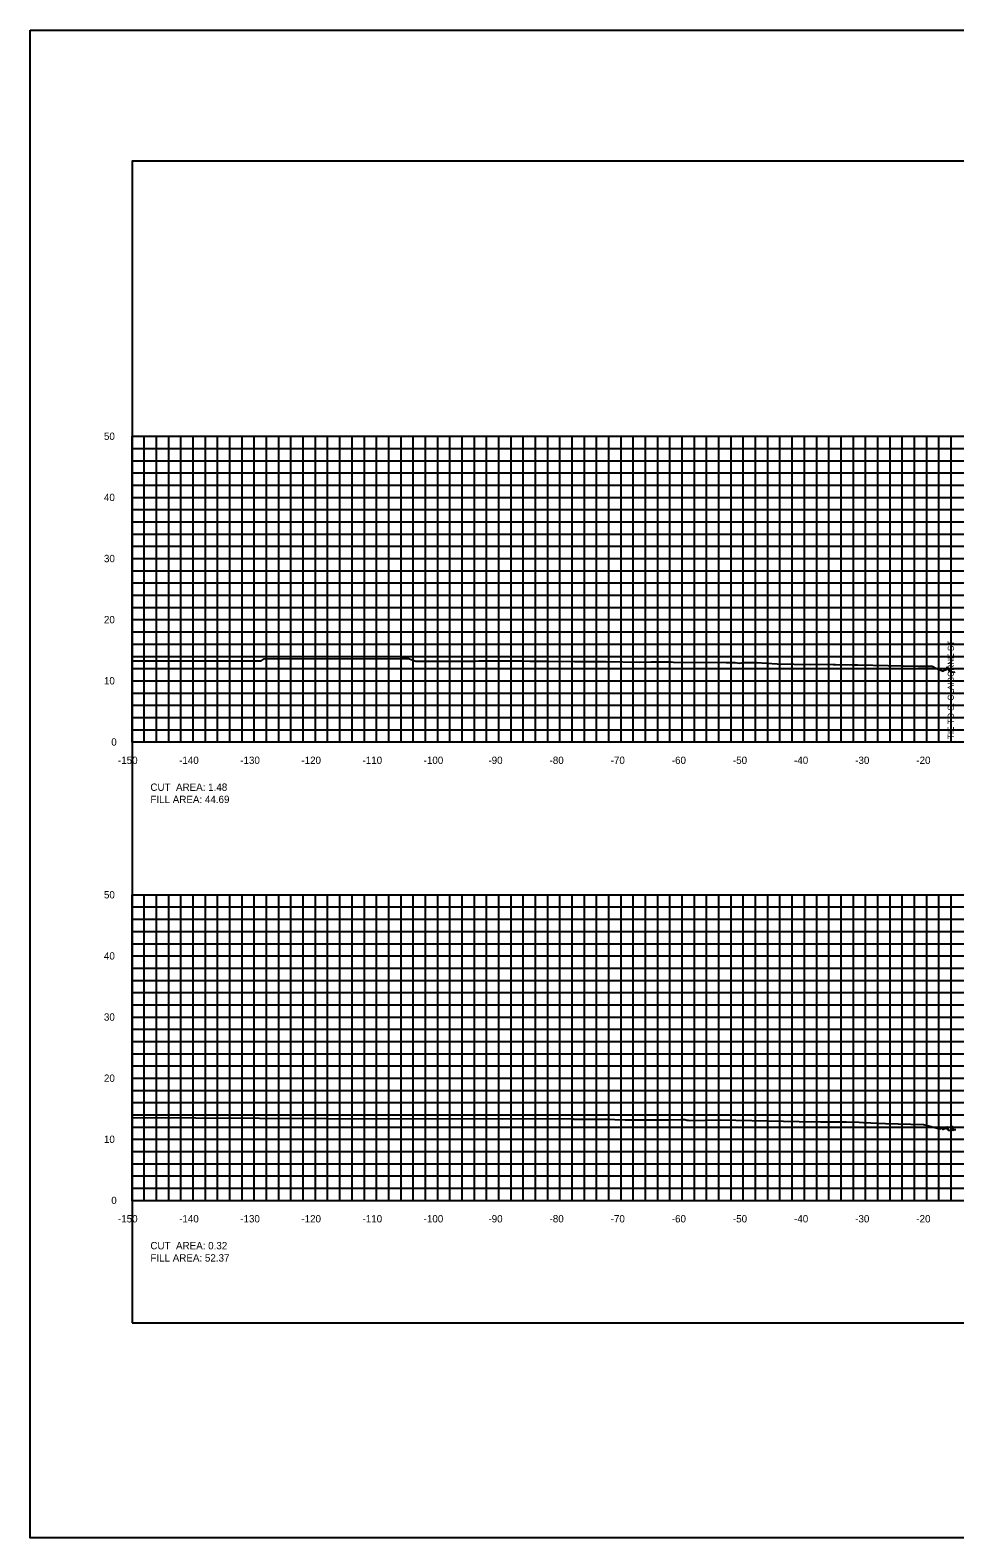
# Model space of a CAD drawing. Extents: x 1797518 to 1804843, y 248068 to 251132.
# Drawn here: x 1804164.3 to 1804315.6, y 250044.2 to 250290.9 of the extents above; entities that cross this region are included whole.
import ezdxf

# ---------------------------------------------------------------- set-up
doc = ezdxf.new("R2010")
doc.units = 0
for name, color, linetype in [('1', 7, 'Continuous'), ('10', 7, 'Continuous'), ('3', 7, 'Continuous'), ('31', 7, 'Continuous'), ('60', 7, 'Continuous'), ('ANNO-TXT', 7, 'Continuous'), ('Level 62', 7, 'Continuous'), ('M-ROADS', 7, 'Continuous')]:
    doc.layers.add(name, color=color, linetype=linetype)

msp = doc.modelspace()

# ---------------------------------------------------------------- linework, layer by layer
msp.add_lwpolyline([(1804181, 250079.43), (1804481, 250079.43), (1804481, 250269.43), (1804181, 250269.43)], close=True)
at = {"layer": '1'}
msp.add_lwpolyline([(1804164.33, 250290.86), (1804501.93, 250290.86), (1804501.93, 250044.24), (1804164.33, 250044.24)], close=True, dxfattribs=at)
at = {"layer": '60'}
for p, q in [((1804180.94, 250224.43), (1804181, 250224.43)), ((1804181, 250174.43), (1804181, 250224.43)), ((1804180.94, 250214.43), (1804181, 250214.43)), ((1804180.94, 250204.43), (1804181, 250204.43)), ((1804180.94, 250194.43), (1804181, 250194.43)), ((1804180.94, 250184.43), (1804181, 250184.43)), ((1804180.94, 250174.43), (1804181, 250174.43)), ((1804181, 250174.43), (1804481, 250174.43)), ((1804181, 250174.37), (1804181, 250174.43)), ((1804191, 250174.37), (1804191, 250174.43)), ((1804201, 250174.37), (1804201, 250174.43)), ((1804211, 250174.37), (1804211, 250174.43)), ((1804221, 250174.37), (1804221, 250174.43)), ((1804231, 250174.37), (1804231, 250174.43)), ((1804241, 250174.37), (1804241, 250174.43)), ((1804251, 250174.37), (1804251, 250174.43)), ((1804261, 250174.37), (1804261, 250174.43)), ((1804271, 250174.37), (1804271, 250174.43)), ((1804281, 250174.37), (1804281, 250174.43)), ((1804291, 250174.37), (1804291, 250174.43)), ((1804301, 250174.37), (1804301, 250174.43)), ((1804311, 250174.37), (1804311, 250174.43)), ((1804180.94, 250149.43), (1804181, 250149.43)), ((1804181, 250099.43), (1804181, 250149.43)), ((1804180.94, 250139.43), (1804181, 250139.43)), ((1804180.94, 250129.43), (1804181, 250129.43)), ((1804180.94, 250119.43), (1804181, 250119.43)), ((1804180.94, 250109.43), (1804181, 250109.43)), ((1804180.94, 250099.43), (1804181, 250099.43)), ((1804181, 250099.43), (1804481, 250099.43)), ((1804181, 250099.37), (1804181, 250099.43)), ((1804191, 250099.37), (1804191, 250099.43)), ((1804201, 250099.37), (1804201, 250099.43)), ((1804211, 250099.37), (1804211, 250099.43)), ((1804221, 250099.37), (1804221, 250099.43)), ((1804231, 250099.37), (1804231, 250099.43)), ((1804241, 250099.37), (1804241, 250099.43)), ((1804251, 250099.37), (1804251, 250099.43)), ((1804261, 250099.37), (1804261, 250099.43)), ((1804271, 250099.37), (1804271, 250099.43)), ((1804281, 250099.37), (1804281, 250099.43)), ((1804291, 250099.37), (1804291, 250099.43)), ((1804301, 250099.37), (1804301, 250099.43)), ((1804311, 250099.37), (1804311, 250099.43))]:
    msp.add_line(p, q, dxfattribs=at)
at = {"layer": 'Level 62'}
for p, q in [((1804181, 250224.43), (1804481, 250224.43)), ((1804181, 250174.43), (1804181, 250224.43)), ((1804183, 250174.43), (1804183, 250224.43)), ((1804185, 250174.43), (1804185, 250224.43)), ((1804187, 250174.43), (1804187, 250224.43)), ((1804189, 250174.43), (1804189, 250224.43)), ((1804191, 250174.43), (1804191, 250224.43)), ((1804193, 250174.43), (1804193, 250224.43)), ((1804195, 250174.43), (1804195, 250224.43)), ((1804197, 250174.43), (1804197, 250224.43)), ((1804199, 250174.43), (1804199, 250224.43)), ((1804201, 250174.43), (1804201, 250224.43)), ((1804203, 250174.43), (1804203, 250224.43)), ((1804205, 250174.43), (1804205, 250224.43)), ((1804207, 250174.43), (1804207, 250224.43)), ((1804209, 250174.43), (1804209, 250224.43)), ((1804211, 250174.43), (1804211, 250224.43)), ((1804213, 250174.43), (1804213, 250224.43)), ((1804215, 250174.43), (1804215, 250224.43)), ((1804217, 250174.43), (1804217, 250224.43)), ((1804219, 250174.43), (1804219, 250224.43)), ((1804221, 250174.43), (1804221, 250224.43)), ((1804223, 250174.43), (1804223, 250224.43)), ((1804225, 250174.43), (1804225, 250224.43)), ((1804227, 250174.43), (1804227, 250224.43)), ((1804229, 250174.43), (1804229, 250224.43)), ((1804231, 250174.43), (1804231, 250224.43)), ((1804233, 250174.43), (1804233, 250224.43)), ((1804235, 250174.43), (1804235, 250224.43)), ((1804237, 250174.43), (1804237, 250224.43)), ((1804239, 250174.43), (1804239, 250224.43)), ((1804241, 250174.43), (1804241, 250224.43)), ((1804243, 250174.43), (1804243, 250224.43)), ((1804245, 250174.43), (1804245, 250224.43)), ((1804247, 250174.43), (1804247, 250224.43)), ((1804249, 250174.43), (1804249, 250224.43)), ((1804251, 250174.43), (1804251, 250224.43)), ((1804253, 250174.43), (1804253, 250224.43)), ((1804255, 250174.43), (1804255, 250224.43)), ((1804257, 250174.43), (1804257, 250224.43)), ((1804259, 250174.43), (1804259, 250224.43)), ((1804261, 250174.43), (1804261, 250224.43)), ((1804263, 250174.43), (1804263, 250224.43)), ((1804265, 250174.43), (1804265, 250224.43)), ((1804267, 250174.43), (1804267, 250224.43)), ((1804269, 250174.43), (1804269, 250224.43)), ((1804271, 250174.43), (1804271, 250224.43)), ((1804273, 250174.43), (1804273, 250224.43)), ((1804275, 250174.43), (1804275, 250224.43)), ((1804277, 250174.43), (1804277, 250224.43)), ((1804279, 250174.43), (1804279, 250224.43)), ((1804281, 250174.43), (1804281, 250224.43)), ((1804283, 250174.43), (1804283, 250224.43)), ((1804285, 250174.43), (1804285, 250224.43)), ((1804287, 250174.43), (1804287, 250224.43)), ((1804289, 250174.43), (1804289, 250224.43)), ((1804291, 250174.43), (1804291, 250224.43)), ((1804293, 250174.43), (1804293, 250224.43)), ((1804295, 250174.43), (1804295, 250224.43)), ((1804297, 250174.43), (1804297, 250224.43)), ((1804299, 250174.43), (1804299, 250224.43)), ((1804301, 250174.43), (1804301, 250224.43)), ((1804303, 250174.43), (1804303, 250224.43)), ((1804305, 250174.43), (1804305, 250224.43)), ((1804307, 250174.43), (1804307, 250224.43)), ((1804309, 250174.43), (1804309, 250224.43)), ((1804311, 250174.43), (1804311, 250224.43)), ((1804313, 250174.43), (1804313, 250224.43)), ((1804315, 250174.43), (1804315, 250224.43)), ((1804181, 250222.43), (1804481, 250222.43)), ((1804181, 250220.43), (1804481, 250220.43)), ((1804181, 250218.43), (1804481, 250218.43)), ((1804181, 250216.43), (1804481, 250216.43)), ((1804181, 250214.43), (1804481, 250214.43)), ((1804181, 250212.43), (1804481, 250212.43)), ((1804181, 250210.43), (1804481, 250210.43)), ((1804181, 250208.43), (1804481, 250208.43)), ((1804181, 250206.43), (1804481, 250206.43)), ((1804181, 250204.43), (1804481, 250204.43)), ((1804181, 250202.43), (1804481, 250202.43)), ((1804181, 250200.43), (1804481, 250200.43)), ((1804181, 250198.43), (1804481, 250198.43)), ((1804181, 250196.43), (1804481, 250196.43)), ((1804181, 250194.43), (1804481, 250194.43)), ((1804181, 250192.43), (1804481, 250192.43)), ((1804181, 250190.43), (1804481, 250190.43)), ((1804181, 250188.43), (1804481, 250188.43)), ((1804181, 250186.43), (1804481, 250186.43)), ((1804181, 250184.43), (1804481, 250184.43)), ((1804181, 250182.43), (1804481, 250182.43)), ((1804181, 250180.43), (1804481, 250180.43)), ((1804181, 250178.43), (1804481, 250178.43)), ((1804181, 250176.43), (1804481, 250176.43)), ((1804181, 250174.43), (1804481, 250174.43)), ((1804181, 250149.43), (1804481, 250149.43)), ((1804181, 250099.43), (1804181, 250149.43)), ((1804181, 250147.43), (1804481, 250147.43)), ((1804183, 250099.43), (1804183, 250149.43)), ((1804185, 250099.43), (1804185, 250149.43)), ((1804187, 250099.43), (1804187, 250149.43)), ((1804189, 250099.43), (1804189, 250149.43)), ((1804191, 250099.43), (1804191, 250149.43)), ((1804193, 250099.43), (1804193, 250149.43)), ((1804195, 250099.43), (1804195, 250149.43)), ((1804197, 250099.43), (1804197, 250149.43)), ((1804199, 250099.43), (1804199, 250149.43)), ((1804201, 250099.43), (1804201, 250149.43)), ((1804203, 250099.43), (1804203, 250149.43)), ((1804205, 250099.43), (1804205, 250149.43)), ((1804207, 250099.43), (1804207, 250149.43)), ((1804209, 250099.43), (1804209, 250149.43)), ((1804211, 250099.43), (1804211, 250149.43)), ((1804213, 250099.43), (1804213, 250149.43)), ((1804215, 250099.43), (1804215, 250149.43)), ((1804217, 250099.43), (1804217, 250149.43)), ((1804219, 250099.43), (1804219, 250149.43)), ((1804221, 250099.43), (1804221, 250149.43)), ((1804223, 250099.43), (1804223, 250149.43)), ((1804225, 250099.43), (1804225, 250149.43)), ((1804227, 250099.43), (1804227, 250149.43)), ((1804229, 250099.43), (1804229, 250149.43)), ((1804231, 250099.43), (1804231, 250149.43)), ((1804233, 250099.43), (1804233, 250149.43)), ((1804235, 250099.43), (1804235, 250149.43)), ((1804237, 250099.43), (1804237, 250149.43)), ((1804239, 250099.43), (1804239, 250149.43)), ((1804241, 250099.43), (1804241, 250149.43)), ((1804243, 250099.43), (1804243, 250149.43)), ((1804245, 250099.43), (1804245, 250149.43)), ((1804247, 250099.43), (1804247, 250149.43)), ((1804249, 250099.43), (1804249, 250149.43)), ((1804251, 250099.43), (1804251, 250149.43)), ((1804253, 250099.43), (1804253, 250149.43)), ((1804255, 250099.43), (1804255, 250149.43)), ((1804257, 250099.43), (1804257, 250149.43)), ((1804259, 250099.43), (1804259, 250149.43)), ((1804261, 250099.43), (1804261, 250149.43)), ((1804263, 250099.43), (1804263, 250149.43)), ((1804265, 250099.43), (1804265, 250149.43)), ((1804267, 250099.43), (1804267, 250149.43)), ((1804269, 250099.43), (1804269, 250149.43)), ((1804271, 250099.43), (1804271, 250149.43)), ((1804273, 250099.43), (1804273, 250149.43)), ((1804275, 250099.43), (1804275, 250149.43)), ((1804277, 250099.43), (1804277, 250149.43)), ((1804279, 250099.43), (1804279, 250149.43)), ((1804281, 250099.43), (1804281, 250149.43)), ((1804283, 250099.43), (1804283, 250149.43)), ((1804285, 250099.43), (1804285, 250149.43)), ((1804287, 250099.43), (1804287, 250149.43)), ((1804289, 250099.43), (1804289, 250149.43)), ((1804291, 250099.43), (1804291, 250149.43)), ((1804293, 250099.43), (1804293, 250149.43)), ((1804295, 250099.43), (1804295, 250149.43)), ((1804297, 250099.43), (1804297, 250149.43)), ((1804299, 250099.43), (1804299, 250149.43)), ((1804301, 250099.43), (1804301, 250149.43)), ((1804303, 250099.43), (1804303, 250149.43)), ((1804305, 250099.43), (1804305, 250149.43)), ((1804307, 250099.43), (1804307, 250149.43)), ((1804309, 250099.43), (1804309, 250149.43)), ((1804311, 250099.43), (1804311, 250149.43)), ((1804313, 250099.43), (1804313, 250149.43)), ((1804315, 250099.43), (1804315, 250149.43)), ((1804181, 250145.43), (1804481, 250145.43)), ((1804181, 250143.43), (1804481, 250143.43)), ((1804181, 250141.43), (1804481, 250141.43)), ((1804181, 250139.43), (1804481, 250139.43)), ((1804181, 250137.43), (1804481, 250137.43)), ((1804181, 250135.43), (1804481, 250135.43)), ((1804181, 250133.43), (1804481, 250133.43)), ((1804181, 250131.43), (1804481, 250131.43)), ((1804181, 250129.43), (1804481, 250129.43)), ((1804181, 250127.43), (1804481, 250127.43)), ((1804181, 250125.43), (1804481, 250125.43)), ((1804181, 250123.43), (1804481, 250123.43)), ((1804181, 250121.43), (1804481, 250121.43)), ((1804181, 250119.43), (1804481, 250119.43)), ((1804181, 250117.43), (1804481, 250117.43)), ((1804181, 250115.43), (1804481, 250115.43)), ((1804181, 250113.43), (1804481, 250113.43)), ((1804181, 250111.43), (1804481, 250111.43)), ((1804181, 250109.43), (1804481, 250109.43)), ((1804181, 250107.43), (1804481, 250107.43)), ((1804181, 250105.43), (1804481, 250105.43)), ((1804181, 250103.43), (1804481, 250103.43)), ((1804181, 250101.43), (1804481, 250101.43)), ((1804181, 250099.43), (1804481, 250099.43))]:
    msp.add_line(p, q, dxfattribs=at)
at = {"layer": 'M-ROADS'}
for points in [[(1804181, 250187.7), (1804184.47, 250187.71), (1804193.98, 250187.7), (1804195.99, 250187.72), (1804197.77, 250187.72), (1804198.56, 250187.71), (1804199.06, 250187.7), (1804199.33, 250187.72), (1804199.46, 250187.71), (1804200.33, 250187.71), (1804202.12, 250187.72), (1804202.62, 250188.02), (1804204.14, 250188.07), (1804204.79, 250188.01), (1804224.98, 250188.1), (1804226.23, 250188.07), (1804227.43, 250187.65), (1804233.85, 250187.63), (1804234.95, 250187.65), (1804235.67, 250187.66), (1804237.05, 250187.66), (1804237.71, 250187.67), (1804238.97, 250187.67), (1804240.2, 250187.68), (1804241.01, 250187.68), (1804242.66, 250187.68), (1804244.09, 250187.67), (1804244.85, 250187.67), (1804246.08, 250187.66), (1804247.67, 250187.65), (1804249.2, 250187.64), (1804253.36, 250187.58), (1804255.76, 250187.59), (1804256.2, 250187.59), (1804257.17, 250187.58), (1804258.01, 250187.58), (1804258.56, 250187.57), (1804264.09, 250187.5), (1804265.95, 250187.53), (1804269.18, 250187.51), (1804269.58, 250187.5), (1804278.2, 250187.44), (1804279.65, 250187.45), (1804280.4, 250187.3), (1804281.03, 250187.45), (1804282.28, 250187.42), (1804283.13, 250187.43), (1804283.18, 250187.41), (1804286.54, 250187.19), (1804292.04, 250187.12), (1804292.88, 250187.13), (1804295.72, 250187.07), (1804296.09, 250187.08), (1804298.83, 250187.04), (1804299.03, 250187.03), (1804299.74, 250187.02), (1804304.69, 250186.95), (1804309.61, 250186.83), (1804311.17, 250186.84), (1804311.92, 250186.83), (1804312.58, 250186.46), (1804313.68, 250186.03), (1804313.74, 250186.05), (1804313.89, 250186.16), (1804313.97, 250186.17), (1804314.02, 250186.2), (1804314.06, 250186.23), (1804314.09, 250186.23), (1804314.11, 250186.25), (1804314.13, 250186.25), (1804314.14, 250186.28), (1804314.16, 250186.28), (1804314.26, 250186.3), (1804314.29, 250186.34), (1804314.29, 250186.36), (1804314.29, 250186.34), (1804314.32, 250186.26), (1804314.34, 250186.64), (1804314.71, 250186), (1804314.94, 250185.86), (1804315.04, 250185.89), (1804315.05, 250185.89), (1804315.05, 250185.89), (1804315.05, 250185.88), (1804315.08, 250185.88), (1804315.09, 250185.87), (1804315.14, 250185.89), (1804315.19, 250185.87), (1804315.46, 250185.85), (1804315.67, 250185.92)], [(1804181, 250112.99), (1804201.87, 250112.87), (1804212.98, 250112.84), (1804241.67, 250112.77), (1804252.81, 250112.82), (1804253.05, 250112.82), (1804253.28, 250112.74), (1804254.52, 250112.73), (1804254.73, 250112.74), (1804254.87, 250112.74), (1804255.14, 250112.74), (1804255.27, 250112.74), (1804255.51, 250112.74), (1804255.75, 250112.74), (1804255.91, 250112.74), (1804256.23, 250112.74), (1804256.51, 250112.74), (1804256.66, 250112.74), (1804256.9, 250112.74), (1804257.32, 250112.73), (1804257.88, 250112.73), (1804258.29, 250112.72), (1804259.17, 250112.7), (1804259.97, 250112.68), (1804261.68, 250112.64), (1804262.98, 250112.63), (1804263.52, 250112.62), (1804267.38, 250112.59), (1804268.84, 250112.62), (1804270.78, 250112.68), (1804271.45, 250112.68), (1804271.78, 250112.55), (1804271.96, 250112.54), (1804272.25, 250112.53), (1804277.23, 250112.59), (1804290.14, 250112.34), (1804293.65, 250112.27), (1804294.63, 250112.26), (1804296.48, 250112.26), (1804297.87, 250112.26), (1804299.94, 250112.22), (1804300.65, 250112.2), (1804304.27, 250111.99), (1804310.45, 250111.83), (1804313.17, 250111.16), (1804313.51, 250111.25), (1804313.65, 250111.04), (1804313.68, 250111.06), (1804313.73, 250111.06), (1804313.78, 250111.16), (1804313.83, 250111.16), (1804314.15, 250111.24), (1804314.24, 250111.34), (1804314.24, 250111.43), (1804314.25, 250111.35), (1804314.34, 250111.1), (1804314.36, 250111.46), (1804314.52, 250110.93), (1804314.8, 250110.93), (1804314.91, 250110.92), (1804314.93, 250110.94), (1804314.94, 250110.95), (1804314.96, 250110.96), (1804314.97, 250110.94), (1804314.99, 250110.93), (1804315.07, 250110.91), (1804315.11, 250110.9), (1804315.16, 250110.92), (1804315.21, 250111.55), (1804315.29, 250110.92), (1804315.45, 250110.97), (1804315.53, 250111.01), (1804315.77, 250111.02)]]:
    msp.add_lwpolyline(points, dxfattribs=at)

# ---------------------------------------------------------------- texts
at = {"layer": '10'}
for s, p in [('-150', (1804178.7, 250170.83)), ('-140', (1804188.7, 250170.83)), ('-130', (1804198.7, 250170.83)), ('-120', (1804208.7, 250170.83)), ('-110', (1804218.7, 250170.83)), ('-100', (1804228.7, 250170.83)), ('-90', (1804239.3, 250170.83)), ('-80', (1804249.3, 250170.83)), ('-70', (1804259.3, 250170.83)), ('-60', (1804269.3, 250170.83)), ('-50', (1804279.3, 250170.83)), ('-40', (1804289.3, 250170.83)), ('-30', (1804299.3, 250170.83)), ('-20', (1804309.3, 250170.83)), ('-150', (1804178.7, 250095.83)), ('-140', (1804188.7, 250095.83)), ('-130', (1804198.7, 250095.83)), ('-120', (1804208.7, 250095.83)), ('-110', (1804218.7, 250095.83)), ('-100', (1804228.7, 250095.83)), ('-90', (1804239.3, 250095.83)), ('-80', (1804249.3, 250095.83)), ('-70', (1804259.3, 250095.83)), ('-60', (1804269.3, 250095.83)), ('-50', (1804279.3, 250095.83)), ('-40', (1804289.3, 250095.83)), ('-30', (1804299.3, 250095.83)), ('-20', (1804309.3, 250095.83))]:
    msp.add_text(s, height=1.2, dxfattribs=at).set_placement(p)
at = {"layer": '3'}
msp.add_text('TIE TO S. CLAIBORNE ST', height=1, rotation=90, dxfattribs=at).set_placement((1804315.44, 250174.87))
at = {"layer": '31'}
for s, p in [('50', (1804176.4, 250223.83)), ('40', (1804176.4, 250213.83)), ('30', (1804176.4, 250203.83)), ('20', (1804176.4, 250193.83)), ('10', (1804176.4, 250183.83)), ('0', (1804177.6, 250173.83)), ('50', (1804176.4, 250148.83)), ('40', (1804176.4, 250138.83)), ('30', (1804176.4, 250128.83)), ('20', (1804176.4, 250118.83)), ('10', (1804176.4, 250108.83)), ('0', (1804177.6, 250098.83))]:
    msp.add_text(s, height=1.2, dxfattribs=at).set_placement(p)
at = {"layer": '60'}
for p in [(1804181, 250174.43), (1804181, 250099.43)]:
    msp.add_text('-', height=0.0001, dxfattribs=at).set_placement(p)
at = {"layer": 'ANNO-TXT'}
for s, p in [('CUT  AREA: 1.48', (1804184, 250166.43)), ('FILL AREA: 44.69', (1804184, 250164.43)), ('CUT  AREA: 0.32', (1804184, 250091.43)), ('FILL AREA: 52.37', (1804184, 250089.43))]:
    msp.add_text(s, height=1.2, dxfattribs=at).set_placement(p)

doc.saveas('drawing.dxf')
